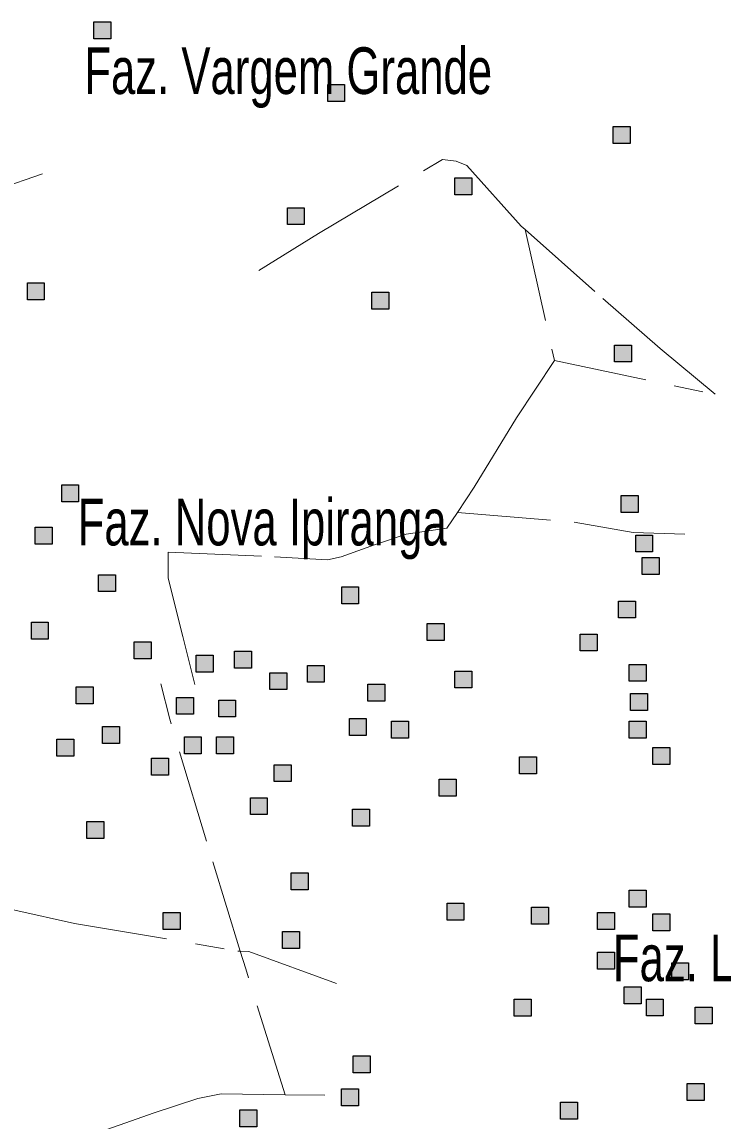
# Model space of a CAD drawing. Extents: x 445.4 to 500, y 8728.7 to 8784.
# Drawn here: x 481.485 to 483.889, y 8738.693 to 8742.463 of the extents above; entities that cross this region are included whole.
import ezdxf

# ---------------------------------------------------------------- set-up
doc = ezdxf.new("R2010")
doc.units = 0
doc.header["$LTSCALE"] = 0.064
doc.linetypes.add('DOT_DASHED', pattern=[7.7, 5, -1.2, 0.3, -1.2])
doc.layers.add('2', color=7, linetype='Continuous', lineweight=25)
doc.layers.add('22', color=7, linetype='DOT_DASHED', lineweight=13)
doc.layers.add('61', color=7, linetype='Continuous')

msp = doc.modelspace()

# ---------------------------------------------------------------- hatches: boundary and pattern name
at = {"layer": '2'}
for points in [[(481.7315, 8742.4631), (481.7895, 8742.4631), (481.7895, 8742.4051), (481.7315, 8742.4051)], [(482.5337, 8742.2482), (482.5917, 8742.2482), (482.5917, 8742.1902), (482.5337, 8742.1902)], [(483.5129, 8742.1048), (483.5709, 8742.1048), (483.5709, 8742.0468), (483.5129, 8742.0468)], [(482.9699, 8741.9282), (483.0279, 8741.9282), (483.0279, 8741.8702), (482.9699, 8741.8702)], [(482.3952, 8741.8259), (482.4532, 8741.8259), (482.4532, 8741.7679), (482.3952, 8741.7679)], [(481.5038, 8741.5678), (481.5618, 8741.5678), (481.5618, 8741.5098), (481.5038, 8741.5098)], [(482.6848, 8741.5361), (482.7428, 8741.5361), (482.7428, 8741.4781), (482.6848, 8741.4781)], [(483.5174, 8741.355), (483.5754, 8741.355), (483.5754, 8741.297), (483.5174, 8741.297)], [(481.6214, 8740.8751), (481.6794, 8740.8751), (481.6794, 8740.8171), (481.6214, 8740.8171)], [(483.54, 8740.8389), (483.598, 8740.8389), (483.598, 8740.7809), (483.54, 8740.7809)], [(481.5309, 8740.7302), (481.5889, 8740.7302), (481.5889, 8740.6722), (481.5309, 8740.6722)], [(483.5898, 8740.7031), (483.6478, 8740.7031), (483.6478, 8740.6451), (483.5898, 8740.6451)], [(483.6124, 8740.6261), (483.6704, 8740.6261), (483.6704, 8740.5681), (483.6124, 8740.5681)], [(481.7481, 8740.5672), (481.8061, 8740.5672), (481.8061, 8740.5092), (481.7481, 8740.5092)], [(482.5816, 8740.5252), (482.6396, 8740.5252), (482.6396, 8740.4672), (482.5816, 8740.4672)], [(483.531, 8740.4767), (483.589, 8740.4767), (483.589, 8740.4187), (483.531, 8740.4187)], [(481.5173, 8740.4043), (481.5753, 8740.4043), (481.5753, 8740.3463), (481.5173, 8740.3463)], [(482.8748, 8740.3997), (482.9328, 8740.3997), (482.9328, 8740.3417), (482.8748, 8740.3417)], [(483.3997, 8740.3635), (483.4577, 8740.3635), (483.4577, 8740.3055), (483.3997, 8740.3055)], [(481.8703, 8740.3363), (481.9283, 8740.3363), (481.9283, 8740.2783), (481.8703, 8740.2783)], [(482.2142, 8740.3047), (482.2722, 8740.3047), (482.2722, 8740.2467), (482.2142, 8740.2467)], [(482.083, 8740.2911), (482.141, 8740.2911), (482.141, 8740.2331), (482.083, 8740.2331)], [(482.3356, 8740.231), (482.3936, 8740.231), (482.3936, 8740.173), (482.3356, 8740.173)], [(482.4638, 8740.2562), (482.5218, 8740.2562), (482.5218, 8740.1982), (482.4638, 8740.1982)], [(482.9699, 8740.2367), (483.0279, 8740.2367), (483.0279, 8740.1787), (482.9699, 8740.1787)], [(483.5672, 8740.2594), (483.6252, 8740.2594), (483.6252, 8740.2014), (483.5672, 8740.2014)], [(482.6712, 8740.1915), (482.7292, 8740.1915), (482.7292, 8740.1335), (482.6712, 8740.1335)], [(481.6712, 8740.1824), (481.7292, 8740.1824), (481.7292, 8740.1244), (481.6712, 8740.1244)], [(483.5717, 8740.1598), (483.6297, 8740.1598), (483.6297, 8740.1018), (483.5717, 8740.1018)], [(482.0151, 8740.1462), (482.0731, 8740.1462), (482.0731, 8740.0882), (482.0151, 8740.0882)], [(482.1599, 8740.1371), (482.2179, 8740.1371), (482.2179, 8740.0791), (482.1599, 8740.0791)], [(482.6079, 8740.0738), (482.6659, 8740.0738), (482.6659, 8740.0158), (482.6079, 8740.0158)], [(481.7617, 8740.0466), (481.8197, 8740.0466), (481.8197, 8739.9886), (481.7617, 8739.9886)], [(482.7527, 8740.0647), (482.8107, 8740.0647), (482.8107, 8740.0067), (482.7527, 8740.0067)], [(483.5672, 8740.0647), (483.6252, 8740.0647), (483.6252, 8740.0067), (483.5672, 8740.0067)], [(481.6051, 8740.0031), (481.6631, 8740.0031), (481.6631, 8739.9451), (481.6051, 8739.9451)], [(482.042, 8740.0107), (482.1, 8740.0107), (482.1, 8739.9527), (482.042, 8739.9527)], [(482.1522, 8740.0107), (482.2102, 8740.0107), (482.2102, 8739.9527), (482.1522, 8739.9527)], [(483.6486, 8739.9741), (483.7066, 8739.9741), (483.7066, 8739.9161), (483.6486, 8739.9161)], [(481.9291, 8739.9379), (481.9871, 8739.9379), (481.9871, 8739.8799), (481.9291, 8739.8799)], [(483.1916, 8739.9425), (483.2496, 8739.9425), (483.2496, 8739.8845), (483.1916, 8739.8845)], [(482.3499, 8739.9153), (482.4079, 8739.9153), (482.4079, 8739.8573), (482.3499, 8739.8573)], [(482.9156, 8739.8655), (482.9736, 8739.8655), (482.9736, 8739.8075), (482.9156, 8739.8075)], [(482.2685, 8739.8021), (482.3265, 8739.8021), (482.3265, 8739.7441), (482.2685, 8739.7441)], [(482.6191, 8739.7623), (482.6771, 8739.7623), (482.6771, 8739.7043), (482.6191, 8739.7043)], [(481.7074, 8739.7206), (481.7654, 8739.7206), (481.7654, 8739.6626), (481.7074, 8739.6626)], [(482.4088, 8739.544), (482.4668, 8739.544), (482.4668, 8739.486), (482.4088, 8739.486)], [(483.5672, 8739.4852), (483.6252, 8739.4852), (483.6252, 8739.4272), (483.5672, 8739.4272)], [(482.9427, 8739.4399), (483.0007, 8739.4399), (483.0007, 8739.3819), (482.9427, 8739.3819)], [(481.9698, 8739.4082), (482.0278, 8739.4082), (482.0278, 8739.3502), (481.9698, 8739.3502)], [(483.2323, 8739.4263), (483.2903, 8739.4263), (483.2903, 8739.3683), (483.2323, 8739.3683)], [(483.4586, 8739.4082), (483.5166, 8739.4082), (483.5166, 8739.3502), (483.4586, 8739.3502)], [(483.6486, 8739.4037), (483.7066, 8739.4037), (483.7066, 8739.3457), (483.6486, 8739.3457)], [(482.3785, 8739.343), (482.4365, 8739.343), (482.4365, 8739.285), (482.3785, 8739.285)], [(483.4586, 8739.2724), (483.5166, 8739.2724), (483.5166, 8739.2144), (483.4586, 8739.2144)], [(483.7131, 8739.2359), (483.7711, 8739.2359), (483.7711, 8739.1779), (483.7131, 8739.1779)], [(483.5503, 8739.1535), (483.6083, 8739.1535), (483.6083, 8739.0955), (483.5503, 8739.0955)], [(483.1735, 8739.1112), (483.2315, 8739.1112), (483.2315, 8739.0532), (483.1735, 8739.0532)], [(483.6263, 8739.1116), (483.6843, 8739.1116), (483.6843, 8739.0536), (483.6263, 8739.0536)], [(483.7934, 8739.084), (483.8514, 8739.084), (483.8514, 8739.026), (483.7934, 8739.026)], [(482.6214, 8738.9165), (482.6794, 8738.9165), (482.6794, 8738.8585), (482.6214, 8738.8585)], [(482.5807, 8738.8033), (482.6387, 8738.8033), (482.6387, 8738.7453), (482.5807, 8738.7453)], [(483.7663, 8738.8214), (483.8243, 8738.8214), (483.8243, 8738.7634), (483.7663, 8738.7634)], [(483.3319, 8738.7579), (483.3899, 8738.7579), (483.3899, 8738.6999), (483.3319, 8738.6999)], [(482.2323, 8738.7309), (482.2903, 8738.7309), (482.2903, 8738.6729), (482.2323, 8738.6729)]]:
    msp.add_hatch(color=256, dxfattribs=at).paths.add_polyline_path(points)

# ---------------------------------------------------------------- linework, layer by layer
for points in [[(481.7315, 8742.4631), (481.7895, 8742.4631), (481.7895, 8742.4051), (481.7315, 8742.4051)], [(482.5337, 8742.2482), (482.5917, 8742.2482), (482.5917, 8742.1902), (482.5337, 8742.1902)], [(483.5129, 8742.1048), (483.5709, 8742.1048), (483.5709, 8742.0468), (483.5129, 8742.0468)], [(482.9699, 8741.9282), (483.0279, 8741.9282), (483.0279, 8741.8702), (482.9699, 8741.8702)], [(482.3952, 8741.8259), (482.4532, 8741.8259), (482.4532, 8741.7679), (482.3952, 8741.7679)], [(481.5038, 8741.5678), (481.5618, 8741.5678), (481.5618, 8741.5098), (481.5038, 8741.5098)], [(482.6848, 8741.5361), (482.7428, 8741.5361), (482.7428, 8741.4781), (482.6848, 8741.4781)], [(483.5174, 8741.355), (483.5754, 8741.355), (483.5754, 8741.297), (483.5174, 8741.297)], [(481.6214, 8740.8751), (481.6794, 8740.8751), (481.6794, 8740.8171), (481.6214, 8740.8171)], [(483.54, 8740.8389), (483.598, 8740.8389), (483.598, 8740.7809), (483.54, 8740.7809)], [(481.5309, 8740.7302), (481.5889, 8740.7302), (481.5889, 8740.6722), (481.5309, 8740.6722)], [(483.5898, 8740.7031), (483.6478, 8740.7031), (483.6478, 8740.6451), (483.5898, 8740.6451)], [(483.6124, 8740.6261), (483.6704, 8740.6261), (483.6704, 8740.5681), (483.6124, 8740.5681)], [(481.7481, 8740.5672), (481.8061, 8740.5672), (481.8061, 8740.5092), (481.7481, 8740.5092)], [(482.5816, 8740.5252), (482.6396, 8740.5252), (482.6396, 8740.4672), (482.5816, 8740.4672)], [(483.531, 8740.4767), (483.589, 8740.4767), (483.589, 8740.4187), (483.531, 8740.4187)], [(481.5173, 8740.4043), (481.5753, 8740.4043), (481.5753, 8740.3463), (481.5173, 8740.3463)], [(482.8748, 8740.3997), (482.9328, 8740.3997), (482.9328, 8740.3417), (482.8748, 8740.3417)], [(483.3997, 8740.3635), (483.4577, 8740.3635), (483.4577, 8740.3055), (483.3997, 8740.3055)], [(481.8703, 8740.3363), (481.9283, 8740.3363), (481.9283, 8740.2783), (481.8703, 8740.2783)], [(482.2142, 8740.3047), (482.2722, 8740.3047), (482.2722, 8740.2467), (482.2142, 8740.2467)], [(482.083, 8740.2911), (482.141, 8740.2911), (482.141, 8740.2331), (482.083, 8740.2331)], [(482.3356, 8740.231), (482.3936, 8740.231), (482.3936, 8740.173), (482.3356, 8740.173)], [(482.4638, 8740.2562), (482.5218, 8740.2562), (482.5218, 8740.1982), (482.4638, 8740.1982)], [(482.9699, 8740.2367), (483.0279, 8740.2367), (483.0279, 8740.1787), (482.9699, 8740.1787)], [(483.5672, 8740.2594), (483.6252, 8740.2594), (483.6252, 8740.2014), (483.5672, 8740.2014)], [(482.6712, 8740.1915), (482.7292, 8740.1915), (482.7292, 8740.1335), (482.6712, 8740.1335)], [(481.6712, 8740.1824), (481.7292, 8740.1824), (481.7292, 8740.1244), (481.6712, 8740.1244)], [(483.5717, 8740.1598), (483.6297, 8740.1598), (483.6297, 8740.1018), (483.5717, 8740.1018)], [(482.0151, 8740.1462), (482.0731, 8740.1462), (482.0731, 8740.0882), (482.0151, 8740.0882)], [(482.1599, 8740.1371), (482.2179, 8740.1371), (482.2179, 8740.0791), (482.1599, 8740.0791)], [(482.6079, 8740.0738), (482.6659, 8740.0738), (482.6659, 8740.0158), (482.6079, 8740.0158)], [(481.7617, 8740.0466), (481.8197, 8740.0466), (481.8197, 8739.9886), (481.7617, 8739.9886)], [(482.7527, 8740.0647), (482.8107, 8740.0647), (482.8107, 8740.0067), (482.7527, 8740.0067)], [(483.5672, 8740.0647), (483.6252, 8740.0647), (483.6252, 8740.0067), (483.5672, 8740.0067)], [(481.6051, 8740.0031), (481.6631, 8740.0031), (481.6631, 8739.9451), (481.6051, 8739.9451)], [(482.042, 8740.0107), (482.1, 8740.0107), (482.1, 8739.9527), (482.042, 8739.9527)], [(482.1522, 8740.0107), (482.2102, 8740.0107), (482.2102, 8739.9527), (482.1522, 8739.9527)], [(483.6486, 8739.9741), (483.7066, 8739.9741), (483.7066, 8739.9161), (483.6486, 8739.9161)], [(481.9291, 8739.9379), (481.9871, 8739.9379), (481.9871, 8739.8799), (481.9291, 8739.8799)], [(483.1916, 8739.9425), (483.2496, 8739.9425), (483.2496, 8739.8845), (483.1916, 8739.8845)], [(482.3499, 8739.9153), (482.4079, 8739.9153), (482.4079, 8739.8573), (482.3499, 8739.8573)], [(482.9156, 8739.8655), (482.9736, 8739.8655), (482.9736, 8739.8075), (482.9156, 8739.8075)], [(482.2685, 8739.8021), (482.3265, 8739.8021), (482.3265, 8739.7441), (482.2685, 8739.7441)], [(482.6191, 8739.7623), (482.6771, 8739.7623), (482.6771, 8739.7043), (482.6191, 8739.7043)], [(481.7074, 8739.7206), (481.7654, 8739.7206), (481.7654, 8739.6626), (481.7074, 8739.6626)], [(482.4088, 8739.544), (482.4668, 8739.544), (482.4668, 8739.486), (482.4088, 8739.486)], [(483.5672, 8739.4852), (483.6252, 8739.4852), (483.6252, 8739.4272), (483.5672, 8739.4272)], [(482.9427, 8739.4399), (483.0007, 8739.4399), (483.0007, 8739.3819), (482.9427, 8739.3819)], [(481.9698, 8739.4082), (482.0278, 8739.4082), (482.0278, 8739.3502), (481.9698, 8739.3502)], [(483.2323, 8739.4263), (483.2903, 8739.4263), (483.2903, 8739.3683), (483.2323, 8739.3683)], [(483.4586, 8739.4082), (483.5166, 8739.4082), (483.5166, 8739.3502), (483.4586, 8739.3502)], [(483.6486, 8739.4037), (483.7066, 8739.4037), (483.7066, 8739.3457), (483.6486, 8739.3457)], [(482.3785, 8739.343), (482.4365, 8739.343), (482.4365, 8739.285), (482.3785, 8739.285)], [(483.4586, 8739.2724), (483.5166, 8739.2724), (483.5166, 8739.2144), (483.4586, 8739.2144)], [(483.7131, 8739.2359), (483.7711, 8739.2359), (483.7711, 8739.1779), (483.7131, 8739.1779)], [(483.5503, 8739.1535), (483.6083, 8739.1535), (483.6083, 8739.0955), (483.5503, 8739.0955)], [(483.1735, 8739.1112), (483.2315, 8739.1112), (483.2315, 8739.0532), (483.1735, 8739.0532)], [(483.6263, 8739.1116), (483.6843, 8739.1116), (483.6843, 8739.0536), (483.6263, 8739.0536)], [(483.7934, 8739.084), (483.8514, 8739.084), (483.8514, 8739.026), (483.7934, 8739.026)], [(482.6214, 8738.9165), (482.6794, 8738.9165), (482.6794, 8738.8585), (482.6214, 8738.8585)], [(482.5807, 8738.8033), (482.6387, 8738.8033), (482.6387, 8738.7453), (482.5807, 8738.7453)], [(483.7663, 8738.8214), (483.8243, 8738.8214), (483.8243, 8738.7634), (483.7663, 8738.7634)], [(483.3319, 8738.7579), (483.3899, 8738.7579), (483.3899, 8738.6999), (483.3319, 8738.6999)], [(482.2323, 8738.7309), (482.2903, 8738.7309), (482.2903, 8738.6729), (482.2323, 8738.6729)]]:
    msp.add_lwpolyline(points, close=True, dxfattribs=at)
at = {"layer": '22'}
msp.add_line((482.524, 8738.7822), (482.3876, 8738.7828), dxfattribs=at)
for points in [[(482.2979, 8741.6111), (482.5017, 8741.7372), (482.9271, 8741.991), (482.9738, 8741.9858), (483.0101, 8741.9703), (483.1968, 8741.7631), (483.2103, 8741.7511)], [(481.5559, 8741.9427), (481.2375, 8741.8317), (480.9855, 8741.7373)], [(483.2103, 8741.7511), (483.4769, 8741.5144), (483.674, 8741.3434), (483.8619, 8741.1864)], [(483.2103, 8741.7511), (483.3109, 8741.302), (483.8615, 8741.186)], [(482.9785, 8740.7808), (483.036, 8740.8669), (483.1812, 8741.1051), (483.3109, 8741.302)], [(481.9869, 8740.6441), (482.3513, 8740.6286), (482.5329, 8740.6182), (482.5795, 8740.6286), (482.6937, 8740.67), (482.8026, 8740.7063), (482.9426, 8740.727), (482.9785, 8740.7808)], [(482.9785, 8740.7808), (483.3784, 8740.7477), (483.5807, 8740.7114), (483.7578, 8740.7061)], [(482.0785, 8740.1904), (482.0368, 8740.3555), (481.9869, 8740.555), (481.9869, 8740.6441)], [(482.2339, 8739.2758), (482.1179, 8739.6536), (481.9919, 8740.0712), (481.9619, 8740.1933)], [(481.3619, 8739.4313), (481.461, 8739.4158), (481.6658, 8739.3709), (482.2252, 8739.2762), (482.2339, 8739.2758)], [(482.2339, 8739.2758), (482.2627, 8739.2745), (482.6316, 8739.1398)], [(482.3876, 8738.7828), (482.2527, 8739.2147), (482.2339, 8739.2758)], [(482.3876, 8738.7828), (482.1678, 8738.7858), (482.0879, 8738.7708), (481.9381, 8738.7209), (481.6984, 8738.6361), (481.6285, 8738.6162), (481.5885, 8738.5114), (481.5347, 8738.3108)]]:
    msp.add_lwpolyline(points, dxfattribs=at)

# ---------------------------------------------------------------- texts
at = {"layer": '61', "width": 0.7}
for s, p in [('Faz. Vargem Grande', (481.6989, 8742.2161)), ('Faz. Nova Ipiranga', (481.6762, 8740.6676)), ('Faz. Lameiro Ferrado', (483.5115, 8739.1726))]:
    msp.add_text(s, height=0.16, dxfattribs=at).set_placement(p)

doc.saveas('drawing.dxf')
